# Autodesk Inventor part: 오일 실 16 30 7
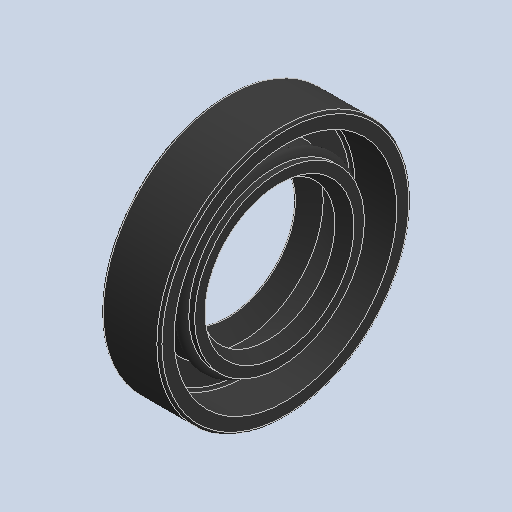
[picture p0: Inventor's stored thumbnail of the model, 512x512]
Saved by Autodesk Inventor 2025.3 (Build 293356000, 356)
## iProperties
Created: 2025-10
Part Number: 오일 실 16 30 7
Material: 고무
Description: 오일-실
Document SubType Name: Modeling
Designer: PC-13
Density: 0.93 g/cm^3
Appearance: 기본값
Author: jhkim
Sending System: Autodesk Inventor 2026
Preprocessor: ST-DEVELOPER v20.1
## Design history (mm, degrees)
feature "Solid1"
node "솔리드1"
